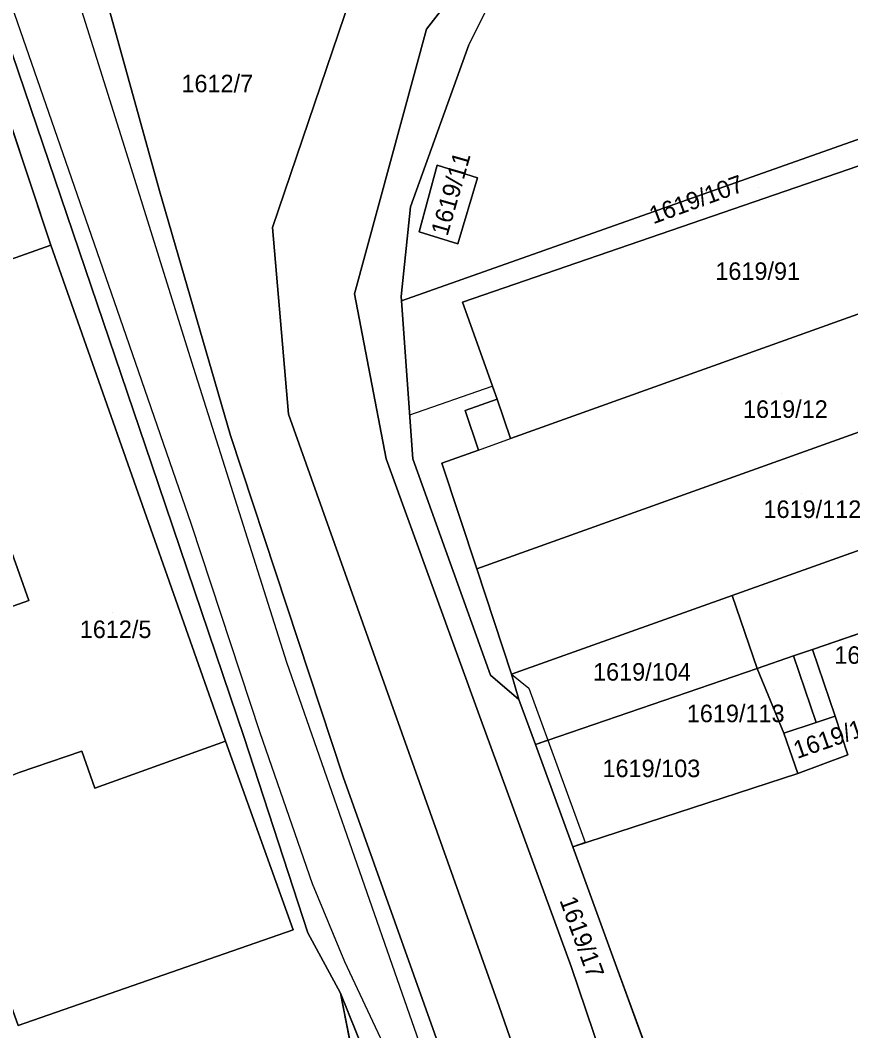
# Model space of a CAD drawing. Extents: x -263943 to -261149, y -1236934 to -1230686.
# Drawn here: x -262385.9 to -262291.1, y -1236658.9 to -1236543.6 of the extents above; entities that cross this region are included whole.
import ezdxf

# ---------------------------------------------------------------- set-up
doc = ezdxf.new("R2010")
doc.units = 0
for name, color, linetype in [('body_kn', 7, 'Continuous'), ('kladpar_druhypozemkov', 7, 'Continuous'), ('kladpar_hranice', 7, 'Continuous'), ('kladpar_parcelnecisla', 7, 'Continuous'), ('kladpar_plochy', 7, 'Continuous'), ('kladpar_sipky', 7, 'Continuous'), ('tarchy_linie', 7, 'Continuous'), ('zappar_hrandruhpozemk', 7, 'Continuous')]:
    doc.layers.add(name, color=color, linetype=linetype)

msp = doc.modelspace()

# ---------------------------------------------------------------- linework, layer by layer
at = {"layer": 'body_kn'}
for p, q in [((-262339.55, -1236544.66), (-262339.55, -1236544.66)), ((-262334.72, -1236546.45), (-262334.72, -1236546.45)), ((-262373.77, -1236558.79), (-262373.77, -1236558.79)), ((-262338.31, -1236560.18), (-262338.31, -1236560.18)), ((-262338.31, -1236560.18), (-262338.31, -1236560.18)), ((-262333.73, -1236561.63), (-262333.73, -1236561.63)), ((-262370, -1236563.13), (-262370, -1236563.13)), ((-262341.38, -1236564.93), (-262341.38, -1236564.93)), ((-262357.1, -1236567.29), (-262357.1, -1236567.29)), ((-262340.37, -1236567.81), (-262340.37, -1236567.81)), ((-262382.41, -1236569.31), (-262382.41, -1236569.31)), ((-262382.41, -1236569.31), (-262382.41, -1236569.31)), ((-262335.95, -1236569.18), (-262335.95, -1236569.18)), ((-262347.77, -1236574.85), (-262347.77, -1236574.85)), ((-262342.42, -1236575.19), (-262342.42, -1236575.19)), ((-262342.39, -1236575.65), (-262342.39, -1236575.65)), ((-262342.39, -1236575.65), (-262342.39, -1236575.65)), ((-262335.45, -1236575.82), (-262335.45, -1236575.82)), ((-262335.45, -1236575.82), (-262335.45, -1236575.82)), ((-262374.51, -1236577.61), (-262374.51, -1236577.61)), ((-262366.33, -1236582.65), (-262366.33, -1236582.65)), ((-262332.03, -1236585.4), (-262332.03, -1236585.4)), ((-262331.49, -1236586.9), (-262331.49, -1236586.9)), ((-262335.14, -1236588.17), (-262335.14, -1236588.17)), ((-262355.27, -1236588.58), (-262355.27, -1236588.58)), ((-262341.46, -1236588.68), (-262341.46, -1236588.68)), ((-262361.9, -1236591.03), (-262361.9, -1236591.03)), ((-262329.95, -1236591.38), (-262329.95, -1236591.38)), ((-262333.62, -1236592.69), (-262333.62, -1236592.69)), ((-262333.62, -1236592.69), (-262333.62, -1236592.69)), ((-262344.15, -1236593.68), (-262344.15, -1236593.68)), ((-262341.1, -1236593.68), (-262341.1, -1236593.68)), ((-262337.79, -1236594.19), (-262337.79, -1236594.19)), ((-262337.79, -1236594.19), (-262337.79, -1236594.19)), ((-262370.9, -1236594.25), (-262370.9, -1236594.25)), ((-262366.39, -1236601.15), (-262366.39, -1236601.15)), ((-262333.81, -1236606.25), (-262333.81, -1236606.25)), ((-262333.81, -1236606.25), (-262333.81, -1236606.25)), ((-262384.9, -1236609.86), (-262384.9, -1236609.86)), ((-262304.66, -1236609.3), (-262304.66, -1236609.3)), ((-262295.51, -1236615.45), (-262295.51, -1236615.45)), ((-262355.47, -1236616.94), (-262355.47, -1236616.94)), ((-262297.65, -1236616.18), (-262297.65, -1236616.18)), ((-262332.22, -1236618.36), (-262332.22, -1236618.36)), ((-262329.84, -1236618.28), (-262329.84, -1236618.28)), ((-262329.84, -1236618.28), (-262329.84, -1236618.28)), ((-262301.8, -1236617.61), (-262301.8, -1236617.61)), ((-262327.88, -1236619.86), (-262327.88, -1236619.86)), ((-262329, -1236621.16), (-262329, -1236621.16)), ((-262329, -1236621.16), (-262329, -1236621.16)), ((-262333.33, -1236623.45), (-262333.33, -1236623.45)), ((-262295.07, -1236623.77), (-262295.07, -1236623.77)), ((-262292.92, -1236623.06), (-262292.92, -1236623.06)), ((-262292.92, -1236623.06), (-262292.92, -1236623.06)), ((-262358.54, -1236624.91), (-262358.54, -1236624.91)), ((-262298.78, -1236625), (-262298.78, -1236625)), ((-262298.78, -1236625), (-262298.78, -1236625)), ((-262362.46, -1236625.89), (-262362.46, -1236625.89)), ((-262360.34, -1236625.47), (-262360.34, -1236625.47)), ((-262327.12, -1236626.3), (-262327.12, -1236626.3)), ((-262327.12, -1236626.3), (-262327.12, -1236626.3)), ((-262325.7, -1236625.81), (-262325.7, -1236625.81)), ((-262378.88, -1236627.04), (-262378.88, -1236627.04)), ((-262291.48, -1236627.47), (-262291.48, -1236627.47)), ((-262297.17, -1236629.58), (-262297.17, -1236629.58)), ((-262349.05, -1236629.97), (-262349.05, -1236629.97)), ((-262377.4, -1236631.26), (-262377.4, -1236631.26)), ((-262322.86, -1236637.95), (-262322.86, -1236637.95)), ((-262322.86, -1236637.95), (-262322.86, -1236637.95)), ((-262321.43, -1236637.48), (-262321.43, -1236637.48)), ((-262352.59, -1236642.15), (-262352.59, -1236642.15)), ((-262354.77, -1236647.43), (-262354.77, -1236647.43)), ((-262353.07, -1236647.77), (-262353.07, -1236647.77)), ((-262318.43, -1236650.08), (-262318.43, -1236650.08)), ((-262348.89, -1236651.03), (-262348.89, -1236651.03)), ((-262323.02, -1236651.61), (-262323.02, -1236651.61)), ((-262342.59, -1236653.88), (-262342.59, -1236653.88)), ((-262349.34, -1236654.64), (-262349.34, -1236654.64)), ((-262331.26, -1236656.18), (-262331.26, -1236656.18))]:
    msp.add_line(p, q, dxfattribs=at)
at = {"layer": 'kladpar_druhypozemkov'}
for p, q in [((-262363.71, -1236550.11), (-262363.71, -1236550.11)), ((-262337.76, -1236562.87), (-262337.76, -1236562.87)), ((-262301.66, -1236562.71), (-262301.66, -1236562.71)), ((-262301.42, -1236570.92), (-262301.42, -1236570.92)), ((-262299.01, -1236586.25), (-262299.01, -1236586.25)), ((-262296.8, -1236597.67), (-262296.8, -1236597.67)), ((-262375.32, -1236611.21), (-262375.32, -1236611.21)), ((-262314.33, -1236617.12), (-262314.33, -1236617.12)), ((-262296.05, -1236618.97), (-262296.05, -1236618.97)), ((-262298.29, -1236621.5), (-262298.29, -1236621.5)), ((-262295.46, -1236625.05), (-262295.46, -1236625.05)), ((-262313.89, -1236627.91), (-262313.89, -1236627.91)), ((-262325.56, -1236642.27), (-262325.56, -1236642.27))]:
    msp.add_line(p, q, dxfattribs=at)
at = {"layer": 'kladpar_hranice'}
for points in [[(-262341.98, -1236672.96), (-262349.34, -1236654.64), (-262353.07, -1236647.77), (-262360.34, -1236625.47), (-262370.9, -1236594.25), (-262387.46, -1236545.56), (-262388.05, -1236543.86), (-262389.82, -1236538.6), (-262392.01, -1236532.49), (-262400.95, -1236505.35), (-262434.5, -1236407.84), (-262435.35, -1236405.56), (-262462.86, -1236327.63), (-262464.77, -1236321.95), (-262464.87, -1236321.66)], [(-262324.57, -1236675.43), (-262331.26, -1236656.18), (-262355.27, -1236588.58), (-262357.1, -1236567.29), (-262346.84, -1236537.03), (-262314.74, -1236499.57), (-262307.25, -1236492.31), (-262298.76, -1236475.97), (-262296.54, -1236459.7), (-262311.13, -1236413.15)], [(-262287.67, -1236474.47), (-262298.27, -1236489.96), (-262302.86, -1236496.31), (-262305.4, -1236499.78), (-262323.54, -1236524.07), (-262339.55, -1236544.66), (-262347.77, -1236574.85), (-262344.15, -1236593.68), (-262333.33, -1236623.45), (-262323.02, -1236651.61), (-262316.25, -1236671.62)], [(-262393.87, -1236485.55), (-262379.01, -1236530.21), (-262376.9, -1236536.58), (-262376.03, -1236541.14), (-262375.9, -1236541.84), (-262370, -1236563.13), (-262361.9, -1236591.03), (-262349.05, -1236629.97), (-262323.5, -1236701.72)], [(-262307.25, -1236492.31), (-262314.74, -1236499.57), (-262346.84, -1236537.03), (-262357.1, -1236567.29), (-262355.27, -1236588.58), (-262331.26, -1236656.18), (-262324.57, -1236675.43), (-262320.6, -1236688.24), (-262310.95, -1236717.07), (-262308.08, -1236725.11), (-262314.12, -1236728.13), (-262323.5, -1236701.72), (-262349.05, -1236629.97), (-262361.9, -1236591.03), (-262370, -1236563.13), (-262375.9, -1236541.84), (-262376.03, -1236541.14), (-262371.14, -1236539.89), (-262339.65, -1236512.86), (-262343.54, -1236506.5), (-262328.69, -1236499.82), (-262307.25, -1236492.31)], [(-262341.38, -1236564.93), (-262334.72, -1236546.45), (-262323.54, -1236524.07), (-262320.66, -1236525.46), (-262317.09, -1236525.94), (-262312.85, -1236525.76), (-262282.2, -1236514.93), (-262269.92, -1236550.04), (-262342.39, -1236575.65)], [(-262300.07, -1236700.2), (-262296.76, -1236709.02), (-262297.28, -1236712.24), (-262301.05, -1236713.72), (-262306.09, -1236700.2), (-262316.25, -1236671.62), (-262323.02, -1236651.61), (-262333.33, -1236623.45), (-262344.15, -1236593.68), (-262347.77, -1236574.85), (-262339.55, -1236544.66), (-262323.54, -1236524.07), (-262334.72, -1236546.45), (-262341.38, -1236564.93), (-262342.42, -1236575.19), (-262342.39, -1236575.65), (-262341.1, -1236593.68), (-262332.22, -1236618.36), (-262329, -1236621.16), (-262327.12, -1236626.3), (-262322.86, -1236637.95), (-262318.43, -1236650.08), (-262311.15, -1236670.01), (-262300.07, -1236700.2)], [(-262426.41, -1236568.94), (-262408.21, -1236557.67), (-262395.88, -1236550.39), (-262387.46, -1236545.56), (-262370.9, -1236594.25), (-262360.34, -1236625.47), (-262353.07, -1236647.77), (-262349.34, -1236654.64), (-262340.9, -1236697.81), (-262341.94, -1236722.48), (-262344.68, -1236743.42), (-262406.98, -1236774.58), (-262426.1, -1236718.72), (-262445.58, -1236662.23), (-262460.81, -1236617.02), (-262415.17, -1236601.27), (-262416.35, -1236597.96), (-262421.51, -1236583.28)], [(-262389.58, -1236547.76), (-262418.67, -1236564.79), (-262408.28, -1236596.1), (-262401.09, -1236616.45), (-262386.12, -1236658.35), (-262354.77, -1236647.43), (-262362.46, -1236625.89), (-262382.41, -1236569.31), (-262389.58, -1236547.76)], [(-262386.12, -1236658.35), (-262401.09, -1236616.45), (-262408.28, -1236596.1), (-262418.67, -1236564.79), (-262389.58, -1236547.76), (-262382.41, -1236569.31), (-262397.43, -1236574.63), (-262384.9, -1236609.86), (-262388.03, -1236610.95), (-262386.83, -1236614.34), (-262390.8, -1236615.75), (-262389.7, -1236618.92), (-262390.64, -1236619.25), (-262390.24, -1236620.44), (-262386.97, -1236629.86), (-262386.03, -1236629.49), (-262378.88, -1236627.04), (-262377.4, -1236631.26), (-262362.46, -1236625.89), (-262354.77, -1236647.43), (-262386.12, -1236658.35)], [(-262329, -1236621.16), (-262332.22, -1236618.36), (-262341.1, -1236593.68), (-262342.39, -1236575.65), (-262269.92, -1236550.04), (-262263.72, -1236567.76), (-262269.3, -1236569.66), (-262274.84, -1236554.97), (-262335.45, -1236575.82), (-262331.49, -1236586.9), (-262335.14, -1236588.17), (-262333.62, -1236592.69), (-262337.79, -1236594.19), (-262333.81, -1236606.25), (-262329.84, -1236618.28), (-262329, -1236621.16)], [(-262335.45, -1236575.82), (-262274.84, -1236554.97), (-262269.3, -1236569.66), (-262329.95, -1236591.38), (-262331.49, -1236586.9), (-262335.45, -1236575.82)], [(-262338.31, -1236560.18), (-262333.73, -1236561.63), (-262335.95, -1236569.18), (-262340.37, -1236567.81), (-262338.31, -1236560.18)], [(-262340.37, -1236567.81), (-262335.95, -1236569.18), (-262333.73, -1236561.63), (-262338.31, -1236560.18), (-262340.37, -1236567.81)], [(-262342.39, -1236575.65), (-262342.42, -1236575.19), (-262341.38, -1236564.93)], [(-262382.41, -1236569.31), (-262362.46, -1236625.89), (-262377.4, -1236631.26), (-262378.88, -1236627.04), (-262386.03, -1236629.49), (-262386.97, -1236629.86), (-262390.24, -1236620.44), (-262390.64, -1236619.25), (-262389.7, -1236618.92), (-262390.8, -1236615.75), (-262386.83, -1236614.34), (-262388.03, -1236610.95), (-262384.9, -1236609.86), (-262397.43, -1236574.63), (-262382.41, -1236569.31)], [(-262337.79, -1236594.19), (-262333.62, -1236592.69), (-262335.14, -1236588.17), (-262331.49, -1236586.9), (-262329.95, -1236591.38), (-262269.3, -1236569.66), (-262264.96, -1236581.59), (-262333.81, -1236606.25), (-262337.79, -1236594.19)], [(-262333.81, -1236606.25), (-262264.96, -1236581.59), (-262260.61, -1236593.58), (-262304.66, -1236609.3), (-262329.84, -1236618.28), (-262333.81, -1236606.25)], [(-262257.57, -1236585.88), (-262252.46, -1236600.65), (-262295.51, -1236615.45), (-262297.65, -1236616.18), (-262301.8, -1236617.61), (-262304.66, -1236609.3), (-262260.61, -1236593.58), (-262259.64, -1236593.24), (-262258.34, -1236592.19), (-262257.59, -1236590.69), (-262257.57, -1236585.88)], [(-262297.28, -1236712.24), (-262296.76, -1236709.02), (-262300.07, -1236700.2), (-262311.15, -1236670.01), (-262318.43, -1236650.08), (-262322.86, -1236637.95), (-262297.17, -1236629.58), (-262291.48, -1236627.47), (-262292.92, -1236623.06), (-262295.51, -1236615.45), (-262252.46, -1236600.65), (-262239.64, -1236637.61), (-262222.87, -1236685.93), (-262248.36, -1236695.07)], [(-262327.12, -1236626.3), (-262329, -1236621.16), (-262329.84, -1236618.28), (-262304.66, -1236609.3), (-262301.8, -1236617.61), (-262327.12, -1236626.3)], [(-262292.92, -1236623.06), (-262295.07, -1236623.77), (-262297.65, -1236616.18), (-262295.51, -1236615.45), (-262292.92, -1236623.06)], [(-262298.78, -1236625), (-262301.8, -1236617.61), (-262297.65, -1236616.18), (-262295.07, -1236623.77), (-262298.78, -1236625)], [(-262322.86, -1236637.95), (-262327.12, -1236626.3), (-262301.8, -1236617.61), (-262298.78, -1236625), (-262297.17, -1236629.58), (-262322.86, -1236637.95)], [(-262298.78, -1236625), (-262295.07, -1236623.77), (-262292.92, -1236623.06), (-262291.48, -1236627.47), (-262297.17, -1236629.58), (-262298.78, -1236625)], [(-262344.68, -1236743.42), (-262341.94, -1236722.48), (-262340.9, -1236697.81), (-262349.34, -1236654.64), (-262341.98, -1236672.96), (-262337.16, -1236697.3), (-262338.38, -1236722.57), (-262340.57, -1236741.36), (-262344.68, -1236743.42)]]:
    msp.add_lwpolyline(points, dxfattribs=at)
at = {"layer": 'kladpar_plochy'}
for p, q in [((-262334.72, -1236546.45), (-262323.54, -1236524.07)), ((-262375.9, -1236541.84), (-262370, -1236563.13)), ((-262387.46, -1236545.56), (-262370.9, -1236594.25)), ((-262370.9, -1236594.25), (-262387.46, -1236545.56)), ((-262341.38, -1236564.93), (-262334.72, -1236546.45)), ((-262382.41, -1236569.31), (-262389.58, -1236547.76)), ((-262269.92, -1236550.04), (-262342.39, -1236575.65)), ((-262338.31, -1236560.18), (-262340.37, -1236567.81)), ((-262333.73, -1236561.63), (-262338.31, -1236560.18)), ((-262335.95, -1236569.18), (-262333.73, -1236561.63)), ((-262370, -1236563.13), (-262361.9, -1236591.03)), ((-262342.42, -1236575.19), (-262341.38, -1236564.93)), ((-262340.37, -1236567.81), (-262335.95, -1236569.18)), ((-262362.46, -1236625.89), (-262382.41, -1236569.31)), ((-262342.39, -1236575.65), (-262342.42, -1236575.19)), ((-262361.9, -1236591.03), (-262349.05, -1236629.97)), ((-262370.9, -1236594.25), (-262360.34, -1236625.47)), ((-262360.34, -1236625.47), (-262370.9, -1236594.25)), ((-262295.51, -1236615.45), (-262252.46, -1236600.65)), ((-262292.92, -1236623.06), (-262295.51, -1236615.45)), ((-262291.48, -1236627.47), (-262292.92, -1236623.06)), ((-262354.77, -1236647.43), (-262362.46, -1236625.89)), ((-262360.34, -1236625.47), (-262353.07, -1236647.77)), ((-262353.07, -1236647.77), (-262360.34, -1236625.47)), ((-262297.17, -1236629.58), (-262291.48, -1236627.47)), ((-262322.86, -1236637.95), (-262297.17, -1236629.58)), ((-262349.05, -1236629.97), (-262323.5, -1236701.72)), ((-262318.43, -1236650.08), (-262322.86, -1236637.95)), ((-262386.12, -1236658.35), (-262354.77, -1236647.43)), ((-262353.07, -1236647.77), (-262349.34, -1236654.64)), ((-262349.34, -1236654.64), (-262353.07, -1236647.77)), ((-262311.15, -1236670.01), (-262318.43, -1236650.08)), ((-262349.34, -1236654.64), (-262340.9, -1236697.81)), ((-262341.98, -1236672.96), (-262349.34, -1236654.64))]:
    msp.add_line(p, q, dxfattribs=at)
for points in [[(-262301.97, -1236405.71), (-262293.72, -1236436.91), (-262288.41, -1236459.63), (-262287.67, -1236474.47), (-262298.27, -1236489.96), (-262302.86, -1236496.31), (-262305.4, -1236499.78), (-262323.54, -1236524.07), (-262339.55, -1236544.66), (-262347.77, -1236574.85), (-262344.15, -1236593.68), (-262333.33, -1236623.45), (-262323.02, -1236651.61), (-262316.25, -1236671.62)], [(-262324.57, -1236675.43), (-262331.26, -1236656.18), (-262355.27, -1236588.58), (-262357.1, -1236567.29), (-262346.84, -1236537.03), (-262314.74, -1236499.57), (-262307.25, -1236492.31), (-262298.76, -1236475.97), (-262296.54, -1236459.7), (-262311.13, -1236413.15)]]:
    msp.add_lwpolyline(points, dxfattribs=at)
for points in [[(-262307.25, -1236492.31), (-262314.74, -1236499.57), (-262346.84, -1236537.03), (-262357.1, -1236567.29), (-262355.27, -1236588.58), (-262331.26, -1236656.18), (-262324.57, -1236675.43), (-262320.6, -1236688.24), (-262310.95, -1236717.07), (-262308.08, -1236725.11), (-262314.12, -1236728.13), (-262323.5, -1236701.72), (-262349.05, -1236629.97), (-262361.9, -1236591.03), (-262370, -1236563.13), (-262375.9, -1236541.84), (-262376.03, -1236541.14), (-262371.14, -1236539.89), (-262339.65, -1236512.86), (-262343.54, -1236506.5), (-262328.69, -1236499.82)], [(-262300.07, -1236700.2), (-262296.76, -1236709.02), (-262297.28, -1236712.24), (-262301.05, -1236713.72), (-262306.09, -1236700.2), (-262316.25, -1236671.62), (-262323.02, -1236651.61), (-262333.33, -1236623.45), (-262344.15, -1236593.68), (-262347.77, -1236574.85), (-262339.55, -1236544.66), (-262323.54, -1236524.07), (-262334.72, -1236546.45), (-262341.38, -1236564.93), (-262342.42, -1236575.19), (-262342.39, -1236575.65), (-262341.1, -1236593.68), (-262332.22, -1236618.36), (-262329, -1236621.16), (-262327.12, -1236626.3), (-262322.86, -1236637.95), (-262318.43, -1236650.08), (-262311.15, -1236670.01)], [(-262386.12, -1236658.35), (-262401.09, -1236616.45), (-262408.28, -1236596.1), (-262418.67, -1236564.79), (-262389.58, -1236547.76), (-262382.41, -1236569.31), (-262397.43, -1236574.63), (-262384.9, -1236609.86), (-262388.03, -1236610.95), (-262386.83, -1236614.34), (-262390.8, -1236615.75), (-262389.7, -1236618.92), (-262390.64, -1236619.25), (-262390.24, -1236620.44), (-262386.97, -1236629.86), (-262386.03, -1236629.49), (-262378.88, -1236627.04), (-262377.4, -1236631.26), (-262362.46, -1236625.89), (-262354.77, -1236647.43)], [(-262329, -1236621.16), (-262332.22, -1236618.36), (-262341.1, -1236593.68), (-262342.39, -1236575.65), (-262269.92, -1236550.04), (-262263.72, -1236567.76), (-262269.3, -1236569.66), (-262274.84, -1236554.97), (-262335.45, -1236575.82), (-262331.49, -1236586.9), (-262335.14, -1236588.17), (-262333.62, -1236592.69), (-262337.79, -1236594.19), (-262333.81, -1236606.25), (-262329.84, -1236618.28)], [(-262335.45, -1236575.82), (-262274.84, -1236554.97), (-262269.3, -1236569.66), (-262329.95, -1236591.38), (-262331.49, -1236586.9)], [(-262338.31, -1236560.18), (-262333.73, -1236561.63), (-262335.95, -1236569.18), (-262340.37, -1236567.81)], [(-262382.41, -1236569.31), (-262362.46, -1236625.89), (-262377.4, -1236631.26), (-262378.88, -1236627.04), (-262386.03, -1236629.49), (-262386.97, -1236629.86), (-262390.24, -1236620.44), (-262390.64, -1236619.25), (-262389.7, -1236618.92), (-262390.8, -1236615.75), (-262386.83, -1236614.34), (-262388.03, -1236610.95), (-262384.9, -1236609.86), (-262397.43, -1236574.63)], [(-262337.79, -1236594.19), (-262333.62, -1236592.69), (-262335.14, -1236588.17), (-262331.49, -1236586.9), (-262329.95, -1236591.38), (-262269.3, -1236569.66), (-262264.96, -1236581.59), (-262333.81, -1236606.25)], [(-262333.81, -1236606.25), (-262264.96, -1236581.59), (-262260.61, -1236593.58), (-262304.66, -1236609.3), (-262329.84, -1236618.28)], [(-262257.57, -1236585.88), (-262252.46, -1236600.65), (-262295.51, -1236615.45), (-262297.65, -1236616.18), (-262301.8, -1236617.61), (-262304.66, -1236609.3), (-262260.61, -1236593.58), (-262259.64, -1236593.24), (-262258.34, -1236592.19), (-262257.59, -1236590.69)], [(-262327.12, -1236626.3), (-262329, -1236621.16), (-262329.84, -1236618.28), (-262304.66, -1236609.3), (-262301.8, -1236617.61)], [(-262292.92, -1236623.06), (-262295.07, -1236623.77), (-262297.65, -1236616.18), (-262295.51, -1236615.45)], [(-262298.78, -1236625), (-262301.8, -1236617.61), (-262297.65, -1236616.18), (-262295.07, -1236623.77)], [(-262322.86, -1236637.95), (-262327.12, -1236626.3), (-262301.8, -1236617.61), (-262298.78, -1236625), (-262297.17, -1236629.58)], [(-262298.78, -1236625), (-262295.07, -1236623.77), (-262292.92, -1236623.06), (-262291.48, -1236627.47), (-262297.17, -1236629.58)], [(-262344.68, -1236743.42), (-262341.94, -1236722.48), (-262340.9, -1236697.81), (-262349.34, -1236654.64), (-262341.98, -1236672.96), (-262337.16, -1236697.3), (-262338.38, -1236722.57), (-262340.57, -1236741.36)]]:
    msp.add_lwpolyline(points, close=True, dxfattribs=at)
at = {"layer": 'kladpar_sipky'}
for p, q in [((-262299.9, -1236619.96), (-262299.9, -1236619.96)), ((-262294.67, -1236620.41), (-262294.67, -1236620.41))]:
    msp.add_line(p, q, dxfattribs=at)
at = {"layer": 'tarchy_linie'}
for points in [[(-262329, -1236621.16), (-262332.22, -1236618.36), (-262341.1, -1236593.68), (-262341.46, -1236588.68), (-262332.03, -1236585.4), (-262331.49, -1236586.9), (-262335.14, -1236588.17), (-262333.62, -1236592.69), (-262337.79, -1236594.19), (-262333.81, -1236606.25), (-262329.84, -1236618.28), (-262329, -1236621.16)], [(-262329.84, -1236618.28), (-262327.88, -1236619.86), (-262325.7, -1236625.81), (-262327.12, -1236626.3), (-262329, -1236621.16), (-262329.84, -1236618.28)], [(-262322.86, -1236637.95), (-262327.12, -1236626.3), (-262325.7, -1236625.81), (-262321.43, -1236637.48), (-262322.86, -1236637.95)]]:
    msp.add_lwpolyline(points, dxfattribs=at)
at = {"layer": 'zappar_hrandruhpozemk'}
for p, q in [((-262366.33, -1236582.65), (-262373.77, -1236558.79)), ((-262333.62, -1236592.69), (-262329.95, -1236591.38)), ((-262366.39, -1236601.15), (-262358.54, -1236624.91))]:
    msp.add_line(p, q, dxfattribs=at)
for points in [[(-262373.77, -1236558.79), (-262381.6, -1236533.82), (-262392.84, -1236500.85)], [(-262388.87, -1236536.33), (-262374.51, -1236577.61), (-262366.39, -1236601.15)], [(-262333.4, -1236680.13), (-262342.59, -1236653.88), (-262355.47, -1236616.94), (-262366.33, -1236582.65)], [(-262358.54, -1236624.91), (-262352.59, -1236642.15), (-262348.89, -1236651.03), (-262341.02, -1236667.83), (-262334.74, -1236681.03)]]:
    msp.add_lwpolyline(points, dxfattribs=at)

# ---------------------------------------------------------------- texts
at = {"layer": 'kladpar_parcelnecisla'}
for s, p in [('1612/7', (-262367.5, -1236551.87)), ('1619/91', (-262306.59, -1236573.28)), ('1619/12', (-262303.43, -1236589.02)), ('1619/112', (-262301.09, -1236600.44)), ('1612/5', (-262379.1, -1236614.14)), ('1619/114', (-262293.01, -1236617.08)), ('1619/104', (-262320.54, -1236619)), ('1619/113', (-262309.84, -1236623.74)), ('1619/103', (-262319.46, -1236630.01))]:
    msp.add_text(s, height=2, dxfattribs=at).set_placement(p)
for s, rotation, p in [('1619/11', 74, (-262337.15, -1236568.36)), ('1619/107', 20, (-262313.67, -1236566.94)), ('1619/13', 19, (-262297.25, -1236627.94)), ('1619/17', 290, (-262324.39, -1236644.05))]:
    msp.add_text(s, height=2, rotation=rotation, dxfattribs=at).set_placement(p)

doc.saveas('drawing.dxf')
